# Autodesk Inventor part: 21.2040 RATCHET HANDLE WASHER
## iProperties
Created: 2007-01
Part Number: 21.2040 RATCHET HANDLE WASHER
Document SubType Name: Modeling
Designer: Andy Moles
Material: Steel
Density: 7.85 g/cm^3
Author: Andy Moles
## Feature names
1. Extrusion1
2. Chamfer1
